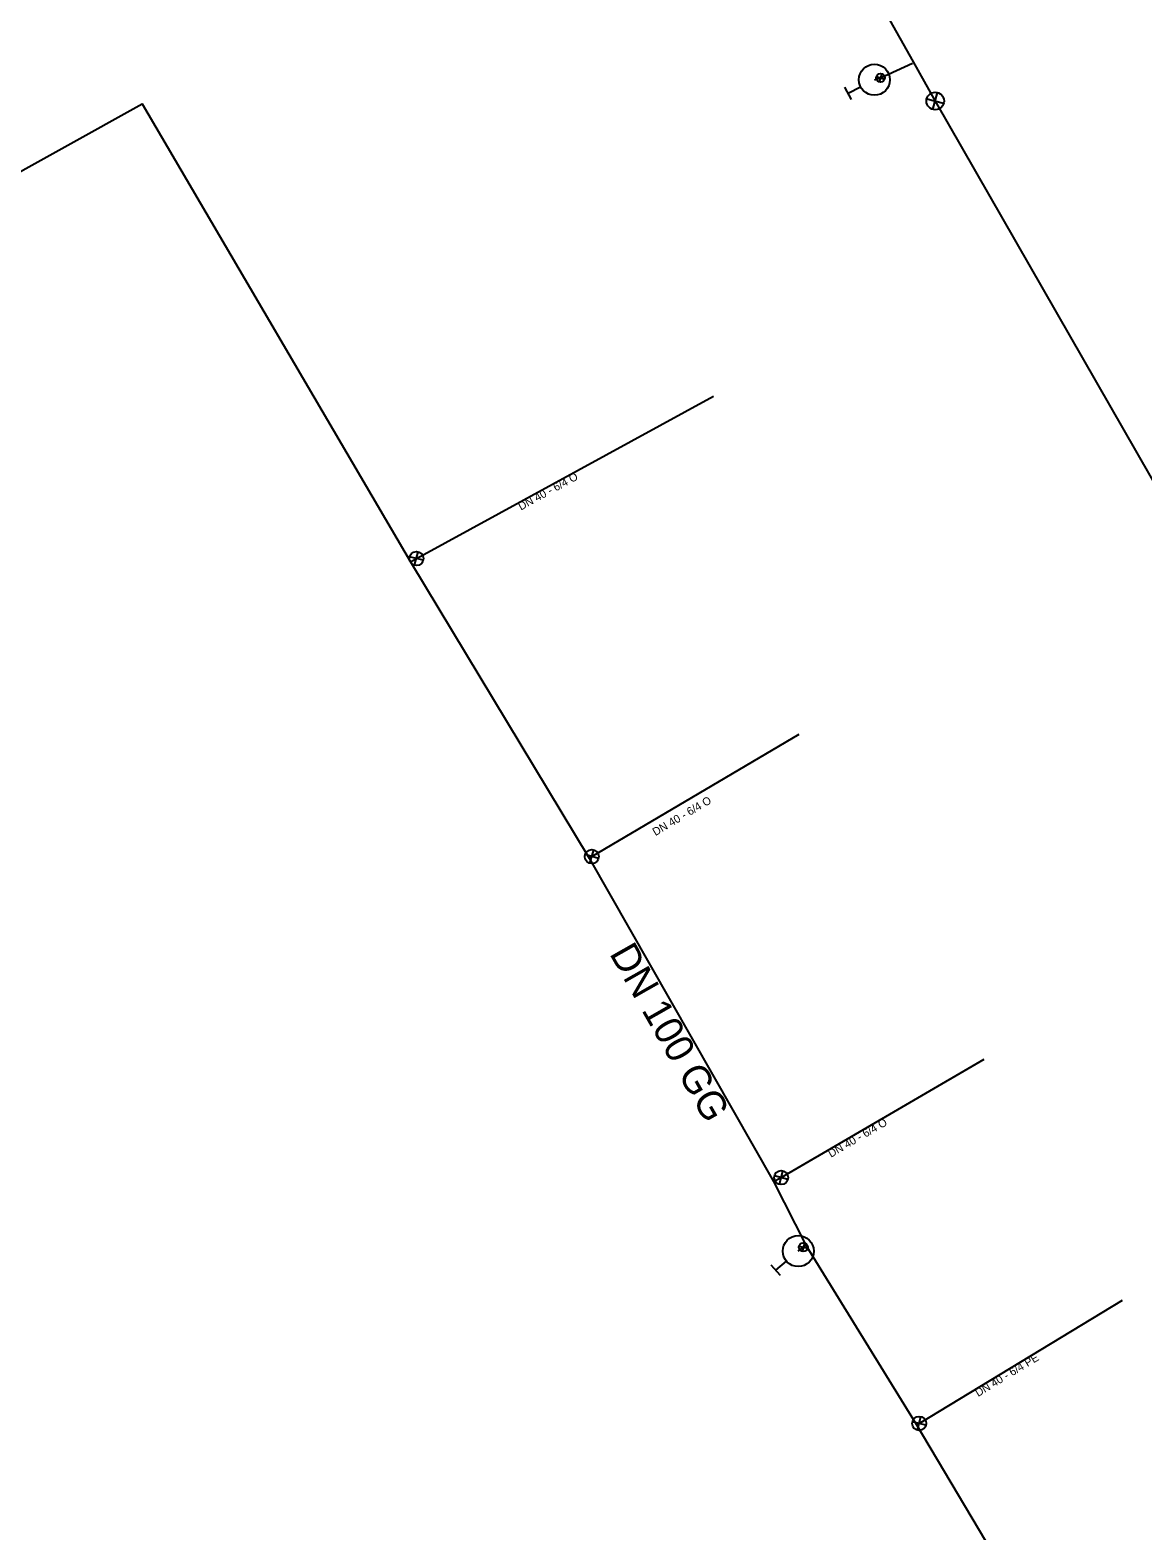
# Model space of a CAD drawing. Extents: x -443562 to -443270, y -1122830 to -1122511.
# Drawn here: x -443428.1 to -443364.9, y -1122675.2 to -1122589.9 of the extents above; entities that cross this region are included whole.
import ezdxf

# ---------------------------------------------------------------- set-up
doc = ezdxf.new("R2010")
doc.units = 0
for name, color, linetype in [('_hydrantova_odbocka_', 7, 'Continuous'), ('_pripojka_priblizne_', 7, 'Continuous'), ('_voda_smvak_prevzato_z_dokumentace_', 7, 'Continuous'), ('Default', 7, 'Continuous'), ('MoLevel 27', 7, 'Continuous'), ('MoLevel 28', 7, 'Continuous'), ('MoLevel 32', 7, 'Continuous'), ('MoLevel 46', 7, 'Continuous'), ('MoLevel 53', 7, 'Continuous')]:
    doc.layers.add(name, color=color, linetype=linetype)

# ---------------------------------------------------------------- blocks, each defined once
blk = doc.blocks.new('_uzaver_')
at = {"layer": 'Default'}
for p, q in [((-0.000035, -0.000035), (0.000035, 0.000035)), ((0.000035, -0.000035), (-0.000035, 0.000035))]:
    blk.add_line(p, q, dxfattribs=at)
for radius in [0.00005, 0.0000025]:
    blk.add_circle((0, 0), radius, dxfattribs=at)
blk = doc.blocks.new('_uzaver_pripojka_')
at = {"layer": 'Default'}
for p, q in [((-0.000035, -0.000035), (0.000035, 0.000035)), ((0.000035, -0.000035), (-0.000035, 0.000035))]:
    blk.add_line(p, q, dxfattribs=at)
for radius in [0.00005, 0.0000025]:
    blk.add_circle((0, 0), radius, dxfattribs=at)
blk = doc.blocks.new('_hydrant_voda_')
at = {"layer": 'Default'}
for p, q in [((-0.0000225, 0.000095), (0.0000225, 0.000095)), ((0, 0.000095), (0, 0.00005))]:
    blk.add_line(p, q, dxfattribs=at)
blk.add_circle((0, 0), 0.00005, dxfattribs=at)

msp = doc.modelspace()

# ---------------------------------------------------------------- linework, layer by layer
at = {"layer": '_hydrantova_odbocka_'}
for points in [[(-443380.14, -1122592.68), (-443379.79, -1122592.57), (-443377.973, -1122591.73)], [(-443384.47, -1122659.3), (-443384.18, -1122659.08), (-443384.03, -1122658.96)]]:
    msp.add_lwpolyline(points, dxfattribs=at)
at = {"layer": '_pripojka_priblizne_'}
for points in [[(-443406.516, -1122620.09), (-443406.18, -1122619.91), (-443389.283, -1122610.683)], [(-443396.35, -1122636.96), (-443396.21, -1122636.86), (-443384.41, -1122629.89)], [(-443385.877, -1122655.347), (-443385.44, -1122655.12), (-443373.891, -1122648.39)], [(-443377.77, -1122669.15), (-443377.59, -1122669.1), (-443366.04, -1122662.09)]]:
    msp.add_lwpolyline(points, dxfattribs=at)
at = {"layer": '_voda_smvak_prevzato_z_dokumentace_'}
for p, q in [((-443423.231, -1122511.082), (-443377.934, -1122591.659)), ((-443377.934, -1122591.659), (-443376.68, -1122593.89)), ((-443376.68, -1122593.89), (-443310.987, -1122708.637))]:
    msp.add_line(p, q, dxfattribs=at)
for points in [[(-443444.123, -1122606.462), (-443421.765, -1122594.051), (-443406.516, -1122620.09), (-443396.35, -1122636.96), (-443385.877, -1122655.347), (-443384.03, -1122658.96)], [(-443384.03, -1122658.96), (-443377.77, -1122669.15), (-443367.13, -1122687.04), (-443361.09, -1122698.23), (-443354.51, -1122710.032), (-443346.631, -1122723.693)]]:
    msp.add_lwpolyline(points, dxfattribs=at)

# ---------------------------------------------------------------- block references
at = {"layer": 'MoLevel 27'}
for p, xscale, yscale, rotation in [((-443379.79, -1122592.57), 5000, 5000.000000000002, -154.1093605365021), ((-443376.68, -1122593.89), 10000, 10000, -60.19985492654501), ((-443384.18, -1122659.08), 5000, 5000, -149.219947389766)]:
    msp.add_blockref('_uzaver_', p, dxfattribs=dict(at, xscale=xscale, yscale=yscale, rotation=rotation))
at = {"layer": 'MoLevel 28'}
for p, xscale, yscale, rotation in [((-443380.14, -1122592.68), 17636.684303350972, 17636.68430335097, 117.24794166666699), ((-443384.47, -1122659.3), 17636.68430335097, 17636.684303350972, 130.67425)]:
    msp.add_blockref('_hydrant_voda_', p, dxfattribs=dict(at, xscale=xscale, yscale=yscale, rotation=rotation))
at = {"layer": 'MoLevel 53'}
for p, xscale, yscale, rotation in [((-443406.18, -1122619.91), 7999.999999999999, 7999.999999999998, 30.080127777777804), ((-443396.21, -1122636.86), 7999.999999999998, 7999.999999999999, 28.7199194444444), ((-443385.44, -1122655.12), 8000, 8000, 30.449233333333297), ((-443377.59, -1122669.1), 7999.999999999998, 8000, 31.25466938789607)]:
    msp.add_blockref('_uzaver_pripojka_', p, dxfattribs=dict(at, xscale=xscale, yscale=yscale, rotation=rotation))

# ---------------------------------------------------------------- texts
at = {"layer": 'MoLevel 32'}
for s, rotation, p in [('DN 40 - 6/4 O', 28.63738, (-443400.238, -1122617.185)), ('DN 40 - 6/4 O', 30.56941, (-443392.589, -1122635.701)), ('DN 40 - 6/4 O', 30.2301, (-443382.608, -1122653.997)), ('DN 40 - 6/4 PE', 31.25389, (-443374.241, -1122667.6))]:
    msp.add_text(s, height=0.455, rotation=rotation, dxfattribs=at).set_placement(p)
at = {"layer": 'MoLevel 46'}
msp.add_text('DN 100 GG', height=1.6049, rotation=299.66512, dxfattribs=at).set_placement((-443395.234, -1122642.373))

doc.saveas('drawing.dxf')
